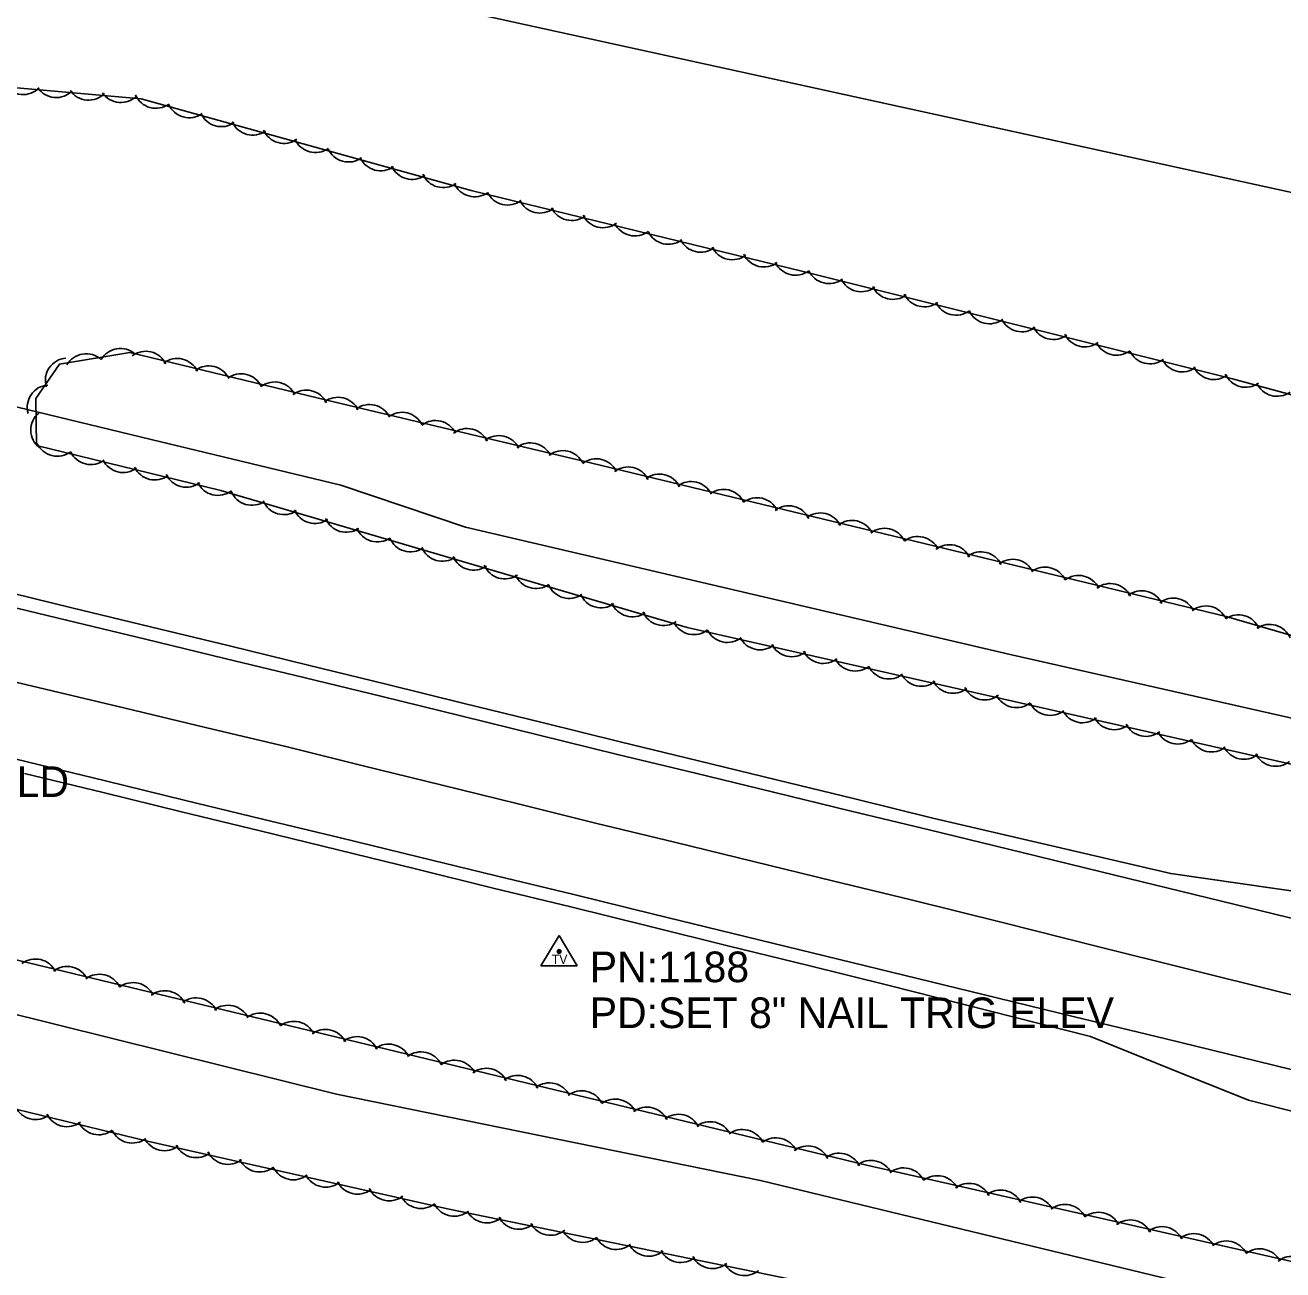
# Model space of a CAD drawing. Extents: x 1441650 to 1491889, y 345904 to 358319.
# Drawn here: x 1459968 to 1460173.4, y 351081.5 to 351284.8 of the extents above; entities that cross this region are included whole.
import ezdxf

# ---------------------------------------------------------------- set-up
doc = ezdxf.new("R2010")
doc.units = 0
for name, color, linetype in [('S_EDGE_PAVEMENT', 7, 'Continuous'), ('S_PAVEMENT_CROWN', 7, 'Continuous'), ('S_SECONDARY_CTL', 7, 'Continuous'), ('S_SECONDARY_CTL_ANNOT', 7, 'Continuous'), ('S_SHOULDER', 7, 'Continuous'), ('S_SIGN_ANNOT', 7, 'Continuous'), ('S_STREAM', 7, 'Continuous'), ('S_TREE', 7, 'Continuous'), ('S_WATER_UTILITIES', 7, 'Continuous')]:
    doc.layers.add(name, color=color, linetype=linetype)

msp = doc.modelspace()

# ---------------------------------------------------------------- linework, layer by layer
at = {"layer": 'S_EDGE_PAVEMENT'}
for points in [[(1459961.82, 351190.72), (1459974.74, 351187.6), (1459987.65, 351184.48), (1460000.57, 351181.36), (1460013.49, 351178.24), (1460026.3, 351175.1), (1460039.11, 351171.96), (1460051.92, 351168.82), (1460064.73, 351165.68), (1460077.45, 351162.59), (1460090.17, 351159.5), (1460102.89, 351156.42), (1460115.61, 351153.33), (1460130.78, 351149.63), (1460145.95, 351145.93), (1460161.12, 351142.23), (1460176.29, 351138.53)], [(1459955.46, 351167.56), (1459968.28, 351164.45), (1459981.1, 351161.33), (1459993.92, 351158.22), (1460006.74, 351155.11), (1460019.46, 351152.02), (1460032.17, 351148.94), (1460044.88, 351145.85), (1460057.6, 351142.77), (1460070.57, 351139.6), (1460083.53, 351136.43), (1460096.5, 351133.26), (1460109.47, 351130.09), (1460124.4, 351126.46), (1460139.32, 351122.83), (1460154.24, 351119.21), (1460169.17, 351115.58), (1460183.82, 351111.99)]]:
    msp.add_lwpolyline(points, dxfattribs=at)
at = {"layer": 'S_PAVEMENT_CROWN'}
msp.add_lwpolyline([(1459958.12, 351179.45), (1459971.23, 351176.33), (1459984.33, 351173.21), (1459997.44, 351170.08), (1460010.55, 351166.96), (1460023.2, 351163.83), (1460035.84, 351160.71), (1460048.48, 351157.58), (1460061.13, 351154.45), (1460074.02, 351151.31), (1460086.91, 351148.18), (1460099.8, 351145.04), (1460112.69, 351141.9), (1460127.79, 351138.14), (1460142.88, 351134.37), (1460157.97, 351130.6), (1460173.06, 351126.84), (1460187.24, 351123.44)], dxfattribs=at)
at = {"layer": 'S_SECONDARY_CTL'}
for p, q in [((1460055.18, 351136.08), (1460052.17, 351131.13)), ((1460055.18, 351136.08), (1460058.13, 351131.13)), ((1460052.17, 351131.13), (1460058.13, 351131.13))]:
    msp.add_line(p, q, dxfattribs=at)
for radius in [0.311, 0.183, 0.103]:
    msp.add_circle((1460055.18, 351133.47), radius, dxfattribs=at)
at = {"layer": 'S_SHOULDER'}
for points in [[(1459962.7, 351192.75), (1459975.58, 351189.62), (1459988.45, 351186.5), (1460001.33, 351183.38), (1460014.2, 351180.25), (1460026.94, 351177.12), (1460039.67, 351173.99), (1460052.41, 351170.86), (1460065.14, 351167.73), (1460077.91, 351164.62), (1460090.68, 351161.51), (1460103.46, 351158.4), (1460116.23, 351155.28), (1460135.64, 351150.74), (1460155.06, 351146.2), (1460177.74, 351142.94)], [(1459967.85, 351162.56), (1459980.69, 351159.43), (1459993.52, 351156.3), (1460006.36, 351153.17), (1460019.04, 351150.06), (1460031.72, 351146.96), (1460044.4, 351143.85), (1460057.08, 351140.75), (1460070.02, 351137.55), (1460082.97, 351134.36), (1460095.92, 351131.17), (1460108.87, 351127.98), (1460125.42, 351123.79), (1460141.97, 351119.59), (1460154.85, 351114.39), (1460167.73, 351109.19), (1460182.07, 351105.54)]]:
    msp.add_lwpolyline(points, dxfattribs=at)
at = {"layer": 'S_STREAM'}
for points in [[(1459929.77, 351231.31), (1459988.56, 351217.1), (1460019.52, 351209.62), (1460039.88, 351202.8), (1460128.82, 351181.99), (1460210.68, 351163.45), (1460237.33, 351154.44), (1460272.6, 351144.09), (1460316.32, 351136.53), (1460351.66, 351130.62), (1460388.19, 351122.01), (1460421.96, 351114.13), (1460434.04, 351113.06), (1460445.65, 351110.73), (1460458.06, 351107.73), (1460466.28, 351103.76), (1460469.26, 351099.4), (1460474.74, 351093.15), (1460478.74, 351086.64), (1460477.67, 351080.2), (1460474.59, 351067.44)], [(1460470.89, 351036.08), (1460468.54, 351025.64), (1460465.31, 351018.05), (1460454.1, 351012.53), (1460442.56, 351011.92), (1460425.79, 351015.97), (1460404, 351023.08), (1460385.24, 351023.17), (1460350.57, 351035.13), (1460315.35, 351045.01), (1460308.43, 351046.03), (1460291.65, 351046.89), (1460271.94, 351051.65), (1460222.23, 351063.67), (1460189.62, 351071.54), (1460088.05, 351096.08), (1460018.83, 351110.19), (1459963.77, 351123.87)]]:
    msp.add_lwpolyline(points, dxfattribs=at)
at = {"layer": 'S_TREE'}
for points in [[(1460494.17, 351129.83), (1460483.97, 351156.12), (1460471.95, 351167.95), (1460454.41, 351173.46), (1460435.25, 351170.91), (1460402.31, 351167.58), (1460357.85, 351178.16), (1460319.41, 351188.83), (1460291.08, 351198.52), (1460243.79, 351205.65), (1460165.12, 351227.03), (1460095.01, 351244.54), (1460040.79, 351257.78), (1459986.9, 351272.74), (1459943.75, 351276.53), (1459905.05, 351278.73)], [(1460179.51, 351162.99), (1460076.07, 351186.4), (1459999.93, 351208.76), (1459969.83, 351216.1), (1459969.72, 351223.8), (1459973.57, 351229.43), (1459985.09, 351231.3), (1460017.48, 351223.47), (1460060.5, 351213.22), (1460164.09, 351188.17), (1460207.37, 351175.61)], [(1459772.91, 351176.4), (1459876.82, 351151.31), (1459954.46, 351135.03), (1460017.3, 351119.86), (1460105.18, 351098.63), (1460206.31, 351075.71), (1460281.6, 351057.51), (1460369.56, 351036.26), (1460401.61, 351029.52), (1460427.04, 351027.44), (1460444.54, 351028.91), (1460451.04, 351031.84), (1460453.09, 351036.3), (1460453.92, 351041.26)], [(1460481.26, 351033.4), (1460484.51, 351019.62), (1460481.49, 351007.42), (1460465.8, 351000.4), (1460406.08, 351003.47), (1460349.69, 351017.1), (1460307.29, 351027.34), (1460275.93, 351036.57), (1460255.18, 351046.58), (1460223.53, 351054.23), (1460174.63, 351064.95), (1460112.28, 351075.97), (1460036.97, 351091.43), (1459987.94, 351102.53), (1459947.12, 351112.39), (1459930.93, 351119.47), (1459908.14, 351125.61), (1459876.29, 351132.41), (1459845.96, 351136.71), (1459817.59, 351140.89), (1459790.62, 351147.27)]]:
    msp.add_lwpolyline(points, dxfattribs=at)
for centre, major_axis, ratio, start_param, end_param in [((1459967.63, 351277.07), (3.63, -0.32), 0.999995, 3.825789, 5.598989), ((1459973.05, 351276.59), (3.63, -0.32), 0.999995, 3.825789, 5.598989), ((1459978.34, 351276.17), (3.63, -0.32), 0.999995, 3.825788, 5.598989), ((1459983.61, 351275.78), (3.63, -0.32), 0.999995, 3.825788, 5.598989), ((1459989.33, 351274.83), (0.1, -3.64), 0.999923, 5.099603, 6.872804), ((1459994.77, 351273.29), (0.1, -3.64), 0.999923, 5.099603, 6.872804), ((1460000.01, 351271.83), (0.1, -3.64), 0.999923, 5.099603, 6.872804), ((1460005.13, 351270.44), (0.1, -3.64), 0.999923, 5.099603, 6.872804), ((1460010.24, 351269.1), (0.1, -3.64), 0.999923, 5.099603, 6.872804), ((1460015.36, 351267.6), (0.1, -3.64), 0.999923, 5.099603, 6.872804), ((1460020.79, 351266.06), (0.1, -3.64), 0.999923, 5.099603, 6.872804), ((1460026.03, 351264.61), (0.1, -3.64), 0.999923, 5.099603, 6.872804), ((1460031.15, 351263.22), (0.1, -3.64), 0.999923, 5.099603, 6.872804), ((1460036.26, 351261.88), (0.1, -3.64), 0.999923, 5.099603, 6.872804), ((1460041.38, 351260.38), (0.1, -3.64), 0.999923, 5.099603, 6.872804), ((1460046.78, 351259.03), (2.69, -2.46), 0.999992, 4.326922, 6.100123), ((1460052.06, 351257.73), (2.69, -2.46), 0.999992, 4.326922, 6.100123), ((1460057.22, 351256.51), (2.69, -2.46), 0.999992, 4.326922, 6.100123), ((1460062.37, 351255.33), (2.69, -2.46), 0.999992, 4.326922, 6.100123), ((1460067.54, 351253.99), (2.69, -2.46), 0.999992, 4.326922, 6.100123), ((1460073.01, 351252.62), (2.69, -2.46), 0.999992, 4.326922, 6.100123), ((1460078.3, 351251.32), (2.69, -2.46), 0.999992, 4.326922, 6.100123), ((1460083.46, 351250.1), (2.69, -2.46), 0.999992, 4.326922, 6.100123), ((1460088.61, 351248.92), (2.69, -2.46), 0.999992, 4.326922, 6.100123), ((1460093.77, 351247.58), (2.69, -2.46), 0.999992, 4.326922, 6.100123), ((1460099.26, 351246.19), (3.53, -0.88), 0.999994, 3.825789, 5.598989), ((1460104.54, 351244.87), (3.53, -0.88), 0.999994, 3.825789, 5.598989), ((1460109.69, 351243.62), (3.53, -0.88), 0.999994, 3.825788, 5.598989), ((1460114.83, 351242.41), (3.53, -0.88), 0.999994, 3.825788, 5.598989), ((1460119.99, 351241.04), (3.53, -0.88), 0.999994, 3.825788, 5.598989), ((1460125.46, 351239.64), (3.53, -0.88), 0.999994, 3.825789, 5.598989), ((1460130.74, 351238.32), (3.53, -0.88), 0.999994, 3.825789, 5.598989), ((1460135.9, 351237.07), (3.53, -0.88), 0.999994, 3.825788, 5.598989), ((1460141.04, 351235.86), (3.53, -0.88), 0.999994, 3.825788, 5.598989), ((1460146.2, 351234.5), (3.53, -0.88), 0.999994, 3.825788, 5.598989), ((1459977.94, 351227.47), (-1.87, 3.12), 0.999877, 5.017224, 6.790425), ((1459983.52, 351228.34), (-1.87, 3.12), 0.999877, 5.017224, 6.790425), ((1459987.66, 351227.86), (0.15, 3.64), 0.999015, 5.20002, 6.973221), ((1460151.67, 351233.1), (3.53, -0.88), 0.999994, 3.825789, 5.598989), ((1459974.92, 351226.75), (-2.06, -3.01), 0.999998, 3.825789, 5.598989), ((1459992.81, 351226.69), (0.15, 3.64), 0.999015, 5.20002, 6.973221), ((1459997.97, 351225.48), (0.15, 3.64), 0.999015, 5.20002, 6.973221), ((1460156.94, 351231.78), (3.53, -0.88), 0.999994, 3.825789, 5.598989), ((1460162.1, 351230.53), (3.53, -0.88), 0.999994, 3.825788, 5.598989), ((1460003.25, 351224.2), (0.15, 3.64), 0.999015, 5.20002, 6.973221), ((1460008.73, 351222.85), (0.15, 3.64), 0.999015, 5.20002, 6.973221), ((1460167.29, 351229.27), (1.58, -3.28), 0.999985, 4.681915, 6.455116), ((1459971.96, 351222.36), (-2.06, -3.01), 0.999998, 3.825788, 5.598989), ((1460013.89, 351221.53), (0.15, 3.64), 0.999015, 5.20002, 6.973221), ((1460172.42, 351227.8), (1.58, -3.28), 0.999985, 4.681915, 6.455116), ((1460019.05, 351220.36), (-0.89, 3.53), 0.999825, 4.915672, 6.688872), ((1460024.22, 351219.17), (-0.89, 3.53), 0.999825, 4.915672, 6.688872), ((1459972.53, 351218.63), (0.98, -3.51), 0.999969, 3.568795, 5.341995), ((1460029.51, 351217.9), (-0.89, 3.53), 0.999825, 4.915672, 6.688872), ((1460034.99, 351216.56), (-0.89, 3.53), 0.999825, 4.915672, 6.688872), ((1460040.16, 351215.25), (-0.89, 3.53), 0.999825, 4.915672, 6.688872), ((1459973.22, 351218.01), (3.6, -0.56), 0.999962, 3.73989, 5.513091), ((1460045.32, 351214.1), (-0.89, 3.53), 0.999825, 4.915672, 6.688872), ((1460050.49, 351212.91), (-0.89, 3.53), 0.999825, 4.915672, 6.688872), ((1459978.7, 351216.64), (3.6, -0.56), 0.999962, 3.73989, 5.513091), ((1460055.78, 351211.64), (-0.89, 3.53), 0.999825, 4.915672, 6.688872), ((1459983.98, 351215.35), (3.6, -0.56), 0.999962, 3.73989, 5.513091), ((1459989.14, 351214.13), (3.6, -0.56), 0.999962, 3.73989, 5.513091), ((1460061.25, 351210.3), (-3.64, 0.17), 0.999961, 3.63593, 5.409131), ((1460066.42, 351208.98), (-3.64, 0.17), 0.999961, 3.63593, 5.409131), ((1459994.29, 351212.95), (3.6, -0.56), 0.999962, 3.73989, 5.513091), ((1459999.46, 351211.62), (3.6, -0.56), 0.999962, 3.73989, 5.513091), ((1460071.57, 351207.8), (-3.64, 0.17), 0.999961, 3.63593, 5.409131), ((1460076.74, 351206.59), (-3.64, 0.17), 0.999961, 3.63593, 5.409131), ((1460005, 351210.01), (3.5, -1.03), 0.99996, 3.825789, 5.598989), ((1460082.02, 351205.31), (-3.64, 0.17), 0.999961, 3.63593, 5.409131), ((1460010.22, 351208.48), (3.5, -1.03), 0.99996, 3.825789, 5.598989), ((1460087.5, 351203.95), (-3.64, 0.17), 0.999961, 3.63593, 5.409131), ((1460092.67, 351202.63), (-3.64, 0.17), 0.999961, 3.63593, 5.409131), ((1460015.32, 351207.02), (3.5, -1.03), 0.99996, 3.825789, 5.598989), ((1460020.41, 351205.6), (3.5, -1.03), 0.99996, 3.825789, 5.598989), ((1460097.82, 351201.46), (-3.64, 0.17), 0.999961, 3.63593, 5.409131), ((1460102.99, 351200.25), (-3.64, 0.17), 0.999961, 3.63593, 5.409131), ((1460025.51, 351204.02), (3.5, -1.03), 0.99996, 3.825789, 5.598989), ((1460108.28, 351198.96), (-3.64, 0.17), 0.999961, 3.63593, 5.409131), ((1460030.91, 351202.4), (3.5, -1.03), 0.99996, 3.825789, 5.598989), ((1460113.76, 351197.61), (-3.64, 0.17), 0.999961, 3.63593, 5.409131), ((1460118.92, 351196.28), (-3.64, 0.17), 0.999961, 3.63593, 5.409131), ((1460036.13, 351200.86), (3.5, -1.03), 0.99996, 3.825789, 5.598989), ((1460041.23, 351199.4), (3.5, -1.03), 0.99996, 3.825789, 5.598989), ((1460124.08, 351195.11), (-3.64, 0.17), 0.999961, 3.63593, 5.409131), ((1460129.24, 351193.9), (-3.64, 0.17), 0.999961, 3.63593, 5.409131), ((1460046.32, 351197.98), (3.5, -1.03), 0.99996, 3.825789, 5.598989), ((1460134.53, 351192.62), (-3.64, 0.17), 0.999961, 3.63593, 5.409131), ((1460051.42, 351196.41), (3.5, -1.03), 0.99996, 3.825789, 5.598989), ((1460140.01, 351191.26), (-3.64, 0.17), 0.999961, 3.63593, 5.409131), ((1460145.18, 351189.93), (-3.64, 0.17), 0.999961, 3.63593, 5.409131), ((1460056.83, 351194.79), (3.5, -1.03), 0.99996, 3.825789, 5.598989), ((1460062.05, 351193.25), (3.5, -1.03), 0.99996, 3.825789, 5.598989), ((1460150.33, 351188.76), (-3.64, 0.17), 0.999961, 3.63593, 5.409131), ((1460067.15, 351191.79), (3.5, -1.03), 0.99996, 3.825789, 5.598989), ((1460155.49, 351187.55), (-3.64, 0.17), 0.999961, 3.63593, 5.409131), ((1460160.78, 351186.27), (-3.64, 0.17), 0.999961, 3.63593, 5.409131), ((1460072.24, 351190.37), (3.5, -1.03), 0.99996, 3.825789, 5.598989), ((1460166.11, 351184.82), (-3.5, 1.02), 0.99996, 3.825789, 5.598989), ((1460077.18, 351188.87), (3.55, -0.8), 0.999963, 3.825789, 5.598989), ((1460082.68, 351187.59), (3.55, -0.8), 0.999963, 3.825789, 5.598989), ((1460171.21, 351183.26), (-3.5, 1.02), 0.99996, 3.825789, 5.598989), ((1460087.99, 351186.39), (3.55, -0.8), 0.999963, 3.825789, 5.598989), ((1460093.17, 351185.26), (3.55, -0.8), 0.999963, 3.825789, 5.598989), ((1460098.34, 351184.16), (3.55, -0.8), 0.999963, 3.825789, 5.598989), ((1460103.52, 351182.91), (3.55, -0.8), 0.999963, 3.825789, 5.598989), ((1460109.02, 351181.63), (3.55, -0.8), 0.999963, 3.825789, 5.598989), ((1460114.33, 351180.43), (3.55, -0.8), 0.999963, 3.825789, 5.598989), ((1460119.51, 351179.3), (3.55, -0.8), 0.999963, 3.825789, 5.598989), ((1460124.68, 351178.2), (3.55, -0.8), 0.999963, 3.825789, 5.598989), ((1460129.87, 351176.95), (3.55, -0.8), 0.999963, 3.825789, 5.598989), ((1460135.37, 351175.67), (3.55, -0.8), 0.999963, 3.825789, 5.598989), ((1460140.67, 351174.47), (3.55, -0.8), 0.999963, 3.825789, 5.598989), ((1460145.85, 351173.33), (3.55, -0.8), 0.999963, 3.825789, 5.598989), ((1460151.02, 351172.24), (3.55, -0.8), 0.999963, 3.825789, 5.598989), ((1460156.21, 351170.99), (3.55, -0.8), 0.999963, 3.825789, 5.598989), ((1460161.71, 351169.71), (3.55, -0.8), 0.999963, 3.825789, 5.598989), ((1460167.01, 351168.51), (3.55, -0.8), 0.999963, 3.825789, 5.598989), ((1460172.2, 351167.37), (3.55, -0.8), 0.999963, 3.825789, 5.598989), ((1459969.67, 351128.66), (-3.52, 0.93), 0.986435, 3.847615, 5.620815), ((1459974.84, 351127.45), (-3.52, 0.93), 0.986435, 3.847615, 5.620815), ((1459980.12, 351126.17), (-3.52, 0.93), 0.986435, 3.847615, 5.620815), ((1459985.61, 351124.81), (-3.52, 0.93), 0.986435, 3.847615, 5.620815), ((1459990.77, 351123.49), (-3.52, 0.93), 0.986435, 3.847615, 5.620815), ((1459995.93, 351122.32), (-3.52, 0.93), 0.986435, 3.847615, 5.620815), ((1460001.09, 351121.11), (-3.52, 0.93), 0.986435, 3.847615, 5.620815), ((1460006.38, 351119.83), (-3.52, 0.93), 0.986435, 3.847615, 5.620815), ((1460011.86, 351118.48), (-3.52, 0.93), 0.986435, 3.847615, 5.620815), ((1460017.03, 351117.16), (-3.54, 0.85), 0.986441, 3.825268, 5.598469), ((1460022.18, 351115.98), (-3.54, 0.85), 0.986441, 3.825268, 5.598469), ((1460027.34, 351114.77), (-3.54, 0.85), 0.986441, 3.825268, 5.598469), ((1460032.63, 351113.49), (-3.54, 0.85), 0.986441, 3.825268, 5.598469), ((1460038.11, 351112.13), (-3.54, 0.85), 0.986441, 3.825268, 5.598469), ((1460043.28, 351110.81), (-3.54, 0.85), 0.986441, 3.825268, 5.598469), ((1460048.43, 351109.64), (-3.54, 0.85), 0.986441, 3.825268, 5.598469), ((1460053.6, 351108.43), (-3.54, 0.85), 0.986441, 3.825268, 5.598469), ((1460058.88, 351107.15), (-3.54, 0.85), 0.986441, 3.825268, 5.598469), ((1460064.36, 351105.79), (-3.54, 0.85), 0.986441, 3.825268, 5.598469), ((1459969.67, 351109.68), (3.6, -0.54), 0.999947, 3.736341, 5.509542), ((1460069.53, 351104.47), (-3.54, 0.85), 0.986441, 3.825268, 5.598469), ((1459974.82, 351108.51), (3.6, -0.54), 0.999947, 3.736341, 5.509542), ((1459979.99, 351107.19), (3.6, -0.54), 0.999947, 3.736341, 5.509542), ((1460074.68, 351103.3), (-3.54, 0.85), 0.986441, 3.825268, 5.598469), ((1460079.85, 351102.09), (-3.54, 0.85), 0.986441, 3.825268, 5.598469), ((1459985.47, 351105.83), (3.6, -0.54), 0.999947, 3.736341, 5.509542), ((1460085.14, 351100.81), (-3.54, 0.85), 0.986441, 3.825268, 5.598469), ((1459990.73, 351104.59), (3.55, -0.8), 0.999947, 3.825789, 5.598989), ((1459995.91, 351103.45), (3.55, -0.8), 0.999947, 3.825789, 5.598989), ((1460090.62, 351099.45), (-3.54, 0.85), 0.986441, 3.825268, 5.598469), ((1460095.79, 351098.13), (-3.54, 0.85), 0.986441, 3.825268, 5.598469), ((1460001.08, 351102.36), (3.55, -0.8), 0.999947, 3.825789, 5.598989), ((1460006.26, 351101.11), (3.55, -0.8), 0.999947, 3.825789, 5.598989), ((1460100.94, 351096.95), (-3.54, 0.85), 0.986441, 3.825268, 5.598469), ((1460106.14, 351095.76), (-3.55, 0.81), 0.986446, 3.825789, 5.598989), ((1460011.76, 351099.83), (3.55, -0.8), 0.999947, 3.825789, 5.598989), ((1460111.45, 351094.55), (-3.55, 0.81), 0.986446, 3.825789, 5.598989), ((1460017.07, 351098.63), (3.55, -0.8), 0.999947, 3.825789, 5.598989), ((1460022.25, 351097.49), (3.55, -0.8), 0.999947, 3.825789, 5.598989), ((1460116.95, 351093.27), (-3.55, 0.81), 0.986446, 3.825789, 5.598989), ((1460122.13, 351092.02), (-3.55, 0.81), 0.986446, 3.825789, 5.598989), ((1460027.42, 351096.4), (3.55, -0.8), 0.999947, 3.825789, 5.598989), ((1460032.61, 351095.15), (3.55, -0.8), 0.999947, 3.825789, 5.598989), ((1460127.3, 351090.92), (-3.55, 0.81), 0.986446, 3.825789, 5.598989), ((1460132.48, 351089.79), (-3.55, 0.81), 0.986446, 3.825789, 5.598989), ((1460038.06, 351093.89), (3.57, -0.73), 0.999948, 3.825789, 5.598989), ((1460043.39, 351092.79), (3.57, -0.73), 0.999948, 3.825789, 5.598989), ((1460137.79, 351088.58), (-3.55, 0.81), 0.986446, 3.825789, 5.598989), ((1460143.29, 351087.3), (-3.55, 0.81), 0.986446, 3.825789, 5.598989), ((1460048.59, 351091.76), (3.57, -0.73), 0.999948, 3.825789, 5.598989), ((1460053.78, 351090.77), (3.57, -0.73), 0.999948, 3.825789, 5.598989), ((1460148.47, 351086.05), (-3.55, 0.81), 0.986446, 3.825789, 5.598989), ((1460058.99, 351089.62), (3.57, -0.73), 0.999948, 3.825789, 5.598989), ((1460153.64, 351084.95), (-3.55, 0.81), 0.986446, 3.825789, 5.598989), ((1460158.82, 351083.81), (-3.55, 0.81), 0.986446, 3.825789, 5.598989), ((1460064.51, 351088.46), (3.57, -0.73), 0.999948, 3.825789, 5.598989), ((1460069.84, 351087.36), (3.57, -0.73), 0.999948, 3.825789, 5.598989), ((1460164.13, 351082.61), (-3.55, 0.81), 0.986446, 3.825789, 5.598989), ((1460169.63, 351081.33), (-3.55, 0.81), 0.986446, 3.825789, 5.598989), ((1460075.05, 351086.33), (3.57, -0.73), 0.999948, 3.825789, 5.598989), ((1460080.24, 351085.34), (3.57, -0.73), 0.999948, 3.825789, 5.598989), ((1460174.82, 351080.08), (-3.55, 0.81), 0.986446, 3.825789, 5.598989), ((1460085.45, 351084.19), (3.57, -0.73), 0.999948, 3.825789, 5.598989)]:
    msp.add_ellipse(centre, major_axis=major_axis, ratio=ratio, start_param=start_param, end_param=end_param, dxfattribs=at)
at = {"layer": 'S_WATER_UTILITIES'}
msp.add_line((1459011.49, 351512.44), (1461680.13, 350927.47), dxfattribs=at)

# ---------------------------------------------------------------- texts
at = {"layer": 'S_SECONDARY_CTL'}
msp.add_text('TV', height=1.5, rotation=360, dxfattribs=at).set_placement((1460053.97, 351131.46))
at = {"layer": 'S_SECONDARY_CTL_ANNOT'}
for s, p in [('PN:1188', (1460060.18, 351128.47)), ('PD:SET 8" NAIL TRIG ELEV', (1460060.18, 351120.97))]:
    msp.add_text(s, height=5, dxfattribs=at).set_placement(p)
at = {"layer": 'S_SIGN_ANNOT'}
msp.add_text('BRIDGE MAY ICE IN COLD', height=5, dxfattribs=at).set_placement((1459891.18, 351158.72))

doc.saveas('drawing.dxf')
